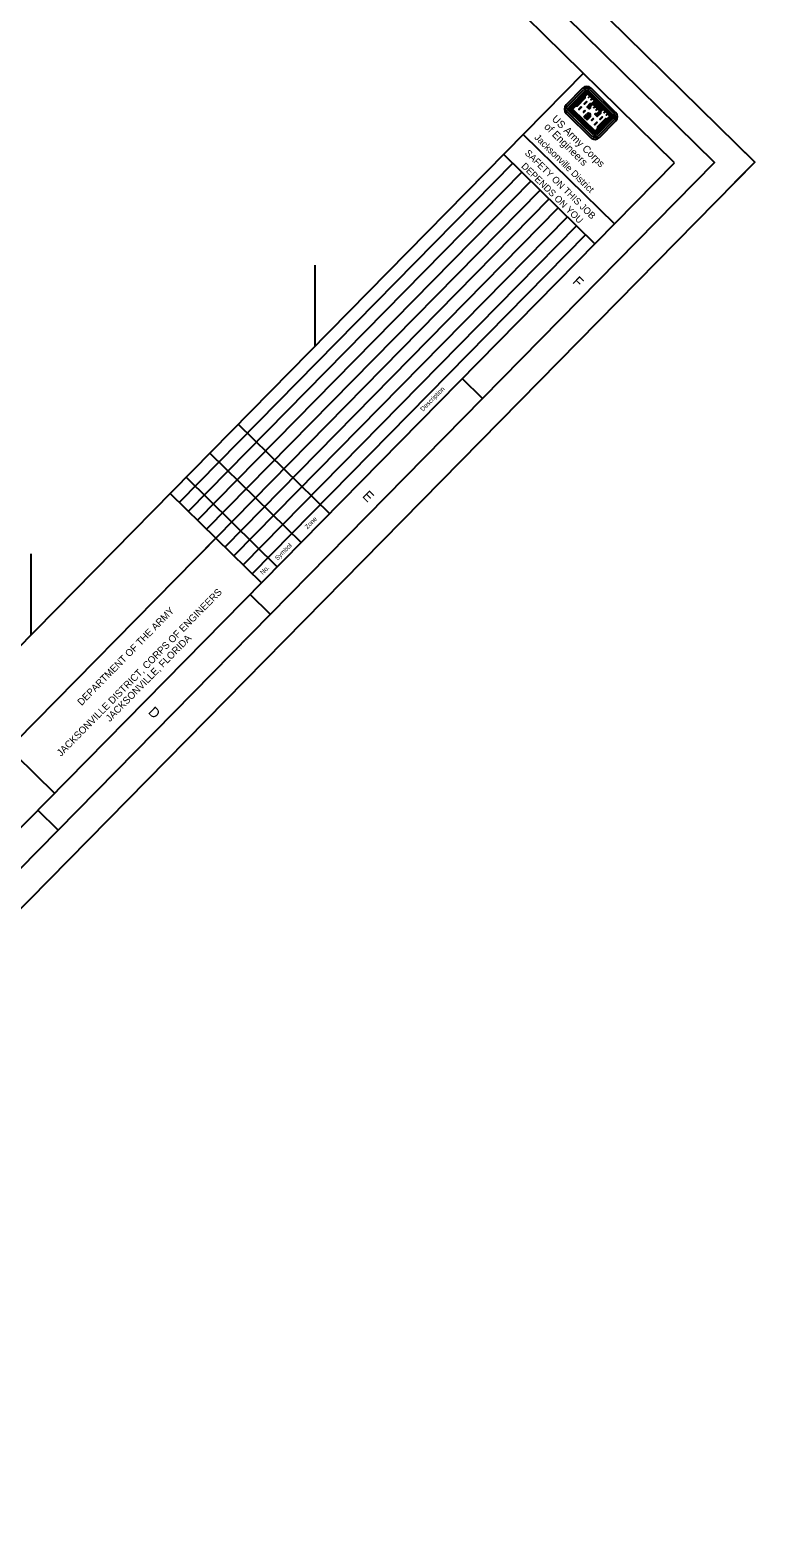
# Model space of a CAD drawing. Extents: x 617253 to 622774, y 776554 to 782063.
# Drawn here: x 621498 to 622774, y 776554 to 779212 of the extents above; entities that cross this region are included whole.
import ezdxf

# ---------------------------------------------------------------- set-up
doc = ezdxf.new("R2010")
doc.units = 0
for name, color, linetype in [('G-ANNO-NPLT', 7, 'Continuous'), ('G-ANNO-TEXT-LOGO', 7, 'Continuous'), ('G-ANNO-TEXT-TTLB', 7, 'Continuous'), ('G-ANNO-TTLB', 7, 'Continuous'), ('V-TOPO-COOR-STAT', 7, 'Continuous')]:
    doc.layers.add(name, color=color, linetype=linetype)

msp = doc.modelspace()

# ---------------------------------------------------------------- linework, layer by layer
at = {"layer": 'G-ANNO-NPLT'}
msp.add_lwpolyline([(619635.8, 782062.9), (622774.3, 778979.1), (620391.4, 776554), (617252.9, 779637.7)], close=True, dxfattribs=at)
msp.add_lwpolyline([(622739.3, 778943.5), (622774.3, 778979.1), (622738.7, 779014.2)], dxfattribs=at)
at = {"layer": 'G-ANNO-TEXT-LOGO'}
for p, q in [((622470.7, 779109.1), (622442, 779079.9)), ((622444.3, 779077.6), (622473, 779106.9)), ((622483.6, 779107), (622527, 779064.3)), ((622529.2, 779066.6), (622485.9, 779109.2)), ((622475.5, 779104.4), (622446.8, 779075.2)), ((622476.1, 779103.8), (622447.4, 779074.5)), ((622476.7, 779103.2), (622448, 779074)), ((622477.4, 779102.6), (622448.6, 779073.3)), ((622478, 779102), (622449.3, 779072.7)), ((622478.6, 779101.3), (622450.1, 779072.3)), ((622479.2, 779100.8), (622451.3, 779072.4)), ((622473.6, 779094.1), (622458.9, 779079.1)), ((622473.6, 779092.8), (622460.2, 779079.2)), ((622522.1, 779059.4), (622478.8, 779102)), ((622522.8, 779060.1), (622479.4, 779102.7)), ((622523.3, 779060.6), (622480, 779103.2)), ((622524, 779061.3), (622480.6, 779103.9)), ((622524.6, 779061.9), (622481.2, 779104.5)), ((622489.6, 779083), (622502.9, 779069.9)), ((622490.3, 779083.6), (622503.5, 779070.6)), ((622490.8, 779084.2), (622504.1, 779071.1)), ((622491.4, 779084.8), (622504.7, 779071.8)), ((622492.1, 779085.5), (622505.3, 779072.4)), ((622492.6, 779086), (622505.9, 779073)), ((622493.3, 779086.7), (622506.5, 779073.6)), ((622442.1, 779064.7), (622485.4, 779022)), ((622487.7, 779024.4), (622444.4, 779067)), ((622490.2, 779026.9), (622446.8, 779069.5)), ((622490.8, 779027.5), (622447.4, 779070.1)), ((622491.4, 779028.1), (622448, 779070.7)), ((622492, 779028.7), (622448.6, 779071.4)), ((622492.6, 779029.3), (622449.2, 779071.9)), ((622492.9, 779030.2), (622450.1, 779072.3)), ((622493, 779031.4), (622451.3, 779072.4)), ((622473.4, 779058.9), (622478.1, 779063.7)), ((622473.4, 779058.9), (622479.1, 779053.3)), ((622474, 779058.4), (622478.7, 779063.1)), ((622474.6, 779057.7), (622479.3, 779062.5)), ((622475.3, 779057.1), (622480, 779061.9)), ((622475.9, 779056.5), (622480.6, 779061.3)), ((622476.7, 779055.7), (622481.4, 779060.5)), ((622477.3, 779055.1), (622482, 779059.9)), ((622477.9, 779054.5), (622482.6, 779059.3)), ((622478.6, 779053.9), (622483.3, 779058.7)), ((622479.1, 779053.3), (622483.8, 779058.1)), ((622521.4, 779059.3), (622492.9, 779030.2)), ((622520.9, 779059.8), (622493, 779031.4)), ((622522.1, 779058.6), (622493.3, 779029.4)), ((622522.7, 779058), (622494, 779028.8)), ((622523.3, 779057.4), (622494.6, 779028.2)), ((622523.9, 779056.8), (622495.2, 779027.6)), ((622524.6, 779056.2), (622495.8, 779026.9)), ((622527, 779053.8), (622498.3, 779024.6)), ((622513, 779054.1), (622499.6, 779040.5)), ((622514.2, 779054), (622499.6, 779039.2)), ((622500.6, 779022.2), (622529.4, 779051.5))]:
    msp.add_line(p, q, dxfattribs=at)
for points in [[(622479.7, 779100.3), (622474.2, 779094.6), (622474.2, 779092.2), (622460.8, 779078.6), (622458.3, 779078.5), (622452.2, 779072.3), (622492.9, 779032.4), (622499, 779038.6), (622499, 779041.1), (622512.4, 779054.7), (622514.8, 779054.7), (622520.4, 779060.3), (622515, 779065.6), (622510.9, 779069.6), (622507, 779073.4), (622501.5, 779067.8), (622501.7, 779065.3), (622496.8, 779060.3), (622493.8, 779063.2), (622494.3, 779063.7), (622496.8, 779063.7), (622502.3, 779069.3), (622496.9, 779074.5), (622492.8, 779078.6), (622489, 779082.3), (622483.5, 779076.8), (622483.6, 779074.2), (622483.1, 779073.7), (622480.1, 779076.7), (622485, 779081.7), (622487.4, 779081.6), (622493, 779087.2), (622487.6, 779092.5), (622483.5, 779096.6), (622479.7, 779100.3)], [(622479.7, 779099.1), (622475, 779094.4), (622475.1, 779091.8), (622461.2, 779077.7), (622458.6, 779077.7), (622453.4, 779072.4), (622493, 779033.6), (622498.1, 779038.8), (622498.1, 779041.5), (622511.9, 779055.6), (622514.5, 779055.5), (622519.2, 779060.2), (622515.3, 779064), (622513.1, 779061.8), (622512.8, 779062.2), (622515, 779064.4), (622511.2, 779068.1), (622509, 779065.9), (622508.7, 779066.2), (622510.9, 779068.4), (622507, 779072.2), (622502.4, 779067.4), (622502.4, 779064.9), (622496.8, 779059.1), (622492.6, 779063.2), (622494, 779064.5), (622496.5, 779064.6), (622501.1, 779069.3), (622497.3, 779073.1), (622495.1, 779070.8), (622494.8, 779071.1), (622497, 779073.3), (622493.1, 779077.1), (622491, 779074.9), (622490.6, 779075.3), (622492.8, 779077.5), (622489, 779081.2), (622484.4, 779076.5), (622484.4, 779073.9), (622483.1, 779072.6), (622478.9, 779076.6), (622484.6, 779082.4), (622487.2, 779082.4), (622491.8, 779087.2), (622488, 779090.9), (622485.8, 779088.7), (622485.5, 779089), (622487.6, 779091.2), (622483.8, 779095), (622481.6, 779092.8), (622481.3, 779093.1), (622483.5, 779095.3), (622479.7, 779099.1)], [(622478, 779085.7), (622473.9, 779081.6), (622474.4, 779081.1), (622478.4, 779085.3), (622478, 779085.7)], [(622486, 779080.7), (622485.3, 779080.7), (622481.3, 779076.7), (622482.7, 779075.3), (622482.7, 779077.2), (622486.2, 779080.7)], [(622468.7, 779076.2), (622464.5, 779072), (622465, 779071.6), (622469.1, 779075.8), (622468.7, 779076.2)], [(622475.2, 779069.8), (622472.4, 779066.8), (622472.7, 779066.5), (622475.6, 779069.4), (622475.2, 779069.8)], [(622489.9, 779055.3), (622487.1, 779052.4), (622486.7, 779052.7), (622489.6, 779055.7), (622489.9, 779055.3)], [(622500.7, 779066.3), (622500.7, 779065.6), (622496.7, 779061.5), (622495.5, 779062.8), (622497.2, 779062.9), (622500.7, 779066.4)], [(622505.8, 779058.4), (622501.7, 779054.3), (622501.3, 779054.6), (622505.4, 779058.8), (622505.8, 779058.4)], [(622496.4, 779048.9), (622492.3, 779044.7), (622491.9, 779045.1), (622496.1, 779049.3), (622496.4, 779048.9)]]:
    msp.add_lwpolyline(points, dxfattribs=at)
for centre, major_axis, start_param, end_param in [((622478.4, 779101.6), (7.64, -7.51), 1.57078, 3.141576), ((622478.4, 779101.6), (5.34, -5.25), 1.57078, 3.141576), ((622478.4, 779101.6), (2.87, -2.82), 1.57078, 3.141576), ((622478.4, 779101.6), (2.25, -2.21), 1.57078, 3.141576), ((622478.4, 779101.6), (1.63, -1.6), 1.57078, 3.141576), ((622478.4, 779101.6), (1.01, -0.99), 1.57078, 3.141576), ((622478.4, 779101.6), (0.389, -0.382), 1.57078, 3.141576), ((622449.6, 779072.3), (-7.64, 7.51), 6.28317, 7.853966), ((622449.6, 779072.3), (-5.34, 5.25), 6.28317, 7.853966), ((622449.6, 779072.3), (-2.87, 2.82), 6.28317, 7.853966), ((622449.6, 779072.3), (-2.25, 2.21), 6.28317, 7.853966), ((622449.6, 779072.3), (-1.63, 1.6), 6.28317, 7.853966), ((622449.6, 779072.3), (-1.01, 0.99), 6.28317, 7.853966), ((622449.6, 779072.3), (-0.389, 0.382), 6.28317, 7.853966), ((622481.7, 779059.5), (-3.96, 3.89), 4.985832, 6.214359), ((622481.7, 779059.5), (-3.34, 3.28), 4.947465, 6.21436), ((622481.7, 779059.5), (-2.72, 2.68), 4.947465, 6.21436), ((622481.7, 779059.5), (-2.1, 2.07), 4.947465, 6.21436), ((622481.7, 779059.5), (-1.48, 1.46), 4.947465, 6.214359), ((622479.6, 779061.6), (1.48, -1.46), 0.068794, 1.335689), ((622479.6, 779061.6), (2.1, -2.07), 0.068794, 1.335689), ((622479.6, 779061.6), (2.72, -2.68), 0.068795, 1.335689), ((622479.6, 779061.6), (3.34, -3.28), 0.068795, 1.335689), ((622479.6, 779061.6), (3.96, -3.89), 0.068795, 1.29842), ((622521.7, 779059), (0.389, -0.382), 6.283169, 7.853965), ((622521.7, 779059), (1.01, -0.99), 6.283169, 7.853965), ((622521.7, 779059), (1.63, -1.6), 6.283169, 7.853965), ((622521.7, 779059), (2.25, -2.21), 6.283169, 7.853965), ((622521.7, 779059), (2.87, -2.82), 6.283169, 7.853965), ((622521.7, 779059), (5.34, -5.25), 6.28317, 7.853966), ((622521.7, 779059), (7.64, -7.51), 6.283169, 7.853965), ((622492.9, 779029.8), (2.87, -2.82), 4.712373, 6.28317), ((622492.9, 779029.8), (2.25, -2.21), 4.712373, 6.28317), ((622492.9, 779029.8), (1.63, -1.6), 4.712373, 6.28317), ((622492.9, 779029.8), (1.01, -0.99), 4.712373, 6.28317), ((622492.9, 779029.8), (0.389, -0.382), 4.712373, 6.28317), ((622492.9, 779029.8), (7.64, -7.51), 4.712373, 6.28317), ((622492.9, 779029.8), (-5.34, 5.25), 1.570781, 3.141577)]:
    msp.add_ellipse(centre, major_axis=major_axis, ratio=0.99964, start_param=start_param, end_param=end_param, dxfattribs=at)
at = {"layer": 'G-ANNO-TTLB'}
for p, q in [((622472.4, 779135.6), (620229.7, 776853.1)), ((622366.4, 779027.7), (622526.9, 778870)), ((622347.9, 778977.1), (621760.7, 778379.4)), ((622331.6, 778993.1), (622492.1, 778835.4)), ((622364, 778961.3), (621776.7, 778363.6)), ((622380, 778945.5), (621792.8, 778347.8)), ((622396.1, 778929.7), (621808.8, 778332.1)), ((622412.1, 778914), (621824.9, 778316.3)), ((622428.2, 778898.2), (621840.9, 778300.5)), ((622444.2, 778882.4), (621856.9, 778284.8)), ((622460.3, 778866.7), (621873, 778269)), ((622476.3, 778850.9), (621889, 778253.2)), ((622294.7, 778562.3), (622259, 778597.4)), ((621864.6, 778517), (622025.1, 778359.3)), ((621814.7, 778466.2), (621975.2, 778308.5)), ((621772.7, 778423.4), (621933.1, 778265.7)), ((621744.7, 778395), (621905.2, 778237.3)), ((621222.1, 777703.5), (621825, 778316.2)), ((621825, 778316.2), (621800.2, 778290.9)), ((621920.9, 778181.9), (621885.2, 778217)), ((621379.8, 778024.7), (621540.9, 777866.5)), ((621547.1, 777801.5), (621511.5, 777836.6))]:
    msp.add_line(p, q, dxfattribs=at)
for points in [[(617323.6, 779638.4), (620390.8, 776624.7), (622703.6, 778978.5), (619636.5, 781992.2)], [(622632.9, 778977.9), (619690.6, 781868.9), (617447.8, 779586.4), (620390.2, 776695.4)]]:
    msp.add_lwpolyline(points, close=True, dxfattribs=at)
at = {"layer": 'V-TOPO-COOR-STAT'}
for p, q in [((622000, 778654.8), (622000, 778797.5)), ((621500, 778146), (621500, 778288.6))]:
    msp.add_line(p, q, dxfattribs=at)

# ---------------------------------------------------------------- texts
at = {"layer": 'G-ANNO-TEXT-TTLB'}
for s, height, rotation, p in [('US Army Corps', 13.086, 315.5037, (622415.8, 779053.8)), ('Jacksonville District', 11.9, 315.5037, (622385.2, 779021.2)), ('of Engineers', 13.086, 315.5037, (622402.2, 779040)), ('SAFETY ON THIS JOB', 11.9, 315.5037, (622368.3, 778993.8)), ('DEPENDS ON YOU', 11.9, 315.5037, (622362.1, 778970.7)), ('Description', 8, 45.5037, (622189.9, 778539)), ('Zone', 8, 45.5037, (621986.4, 778331.4)), ('Symbol', 8, 45.5037, (621933.7, 778276.2)), ('No.', 8, 45.5037, (621907.7, 778251.1)), ('JACKSONVILLE DISTRICT, CORPS OF ENGINEERS', 12.5, 45.5037, (621552.4, 777930.5)), ('DEPARTMENT OF THE ARMY', 12.5, 45.5037, (621588.6, 778020.1)), ('JACKSONVILLE, FLORIDA', 12.5, 45.5037, (621638.3, 777991.6))]:
    msp.add_text(s, height=height, rotation=rotation, dxfattribs=at).set_placement(p)
at = {"layer": 'G-ANNO-TTLB'}
for s, p in [('F', (622451.9, 778766.9)), ('E', (622081.9, 778389.2)), ('D', (621704.5, 778008.3))]:
    msp.add_text(s, height=17.5, rotation=315.5037, dxfattribs=at).set_placement(p)

doc.saveas('drawing.dxf')
